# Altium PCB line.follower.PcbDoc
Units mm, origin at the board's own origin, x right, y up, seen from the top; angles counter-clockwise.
Board outline 60.32 x 63.12 mm, 2 copper layers (Top Layer, Bottom Layer); 13 components, 26 nets, 91 pads, 0 vias.
Unrouted connection lines stored in the file: 2.
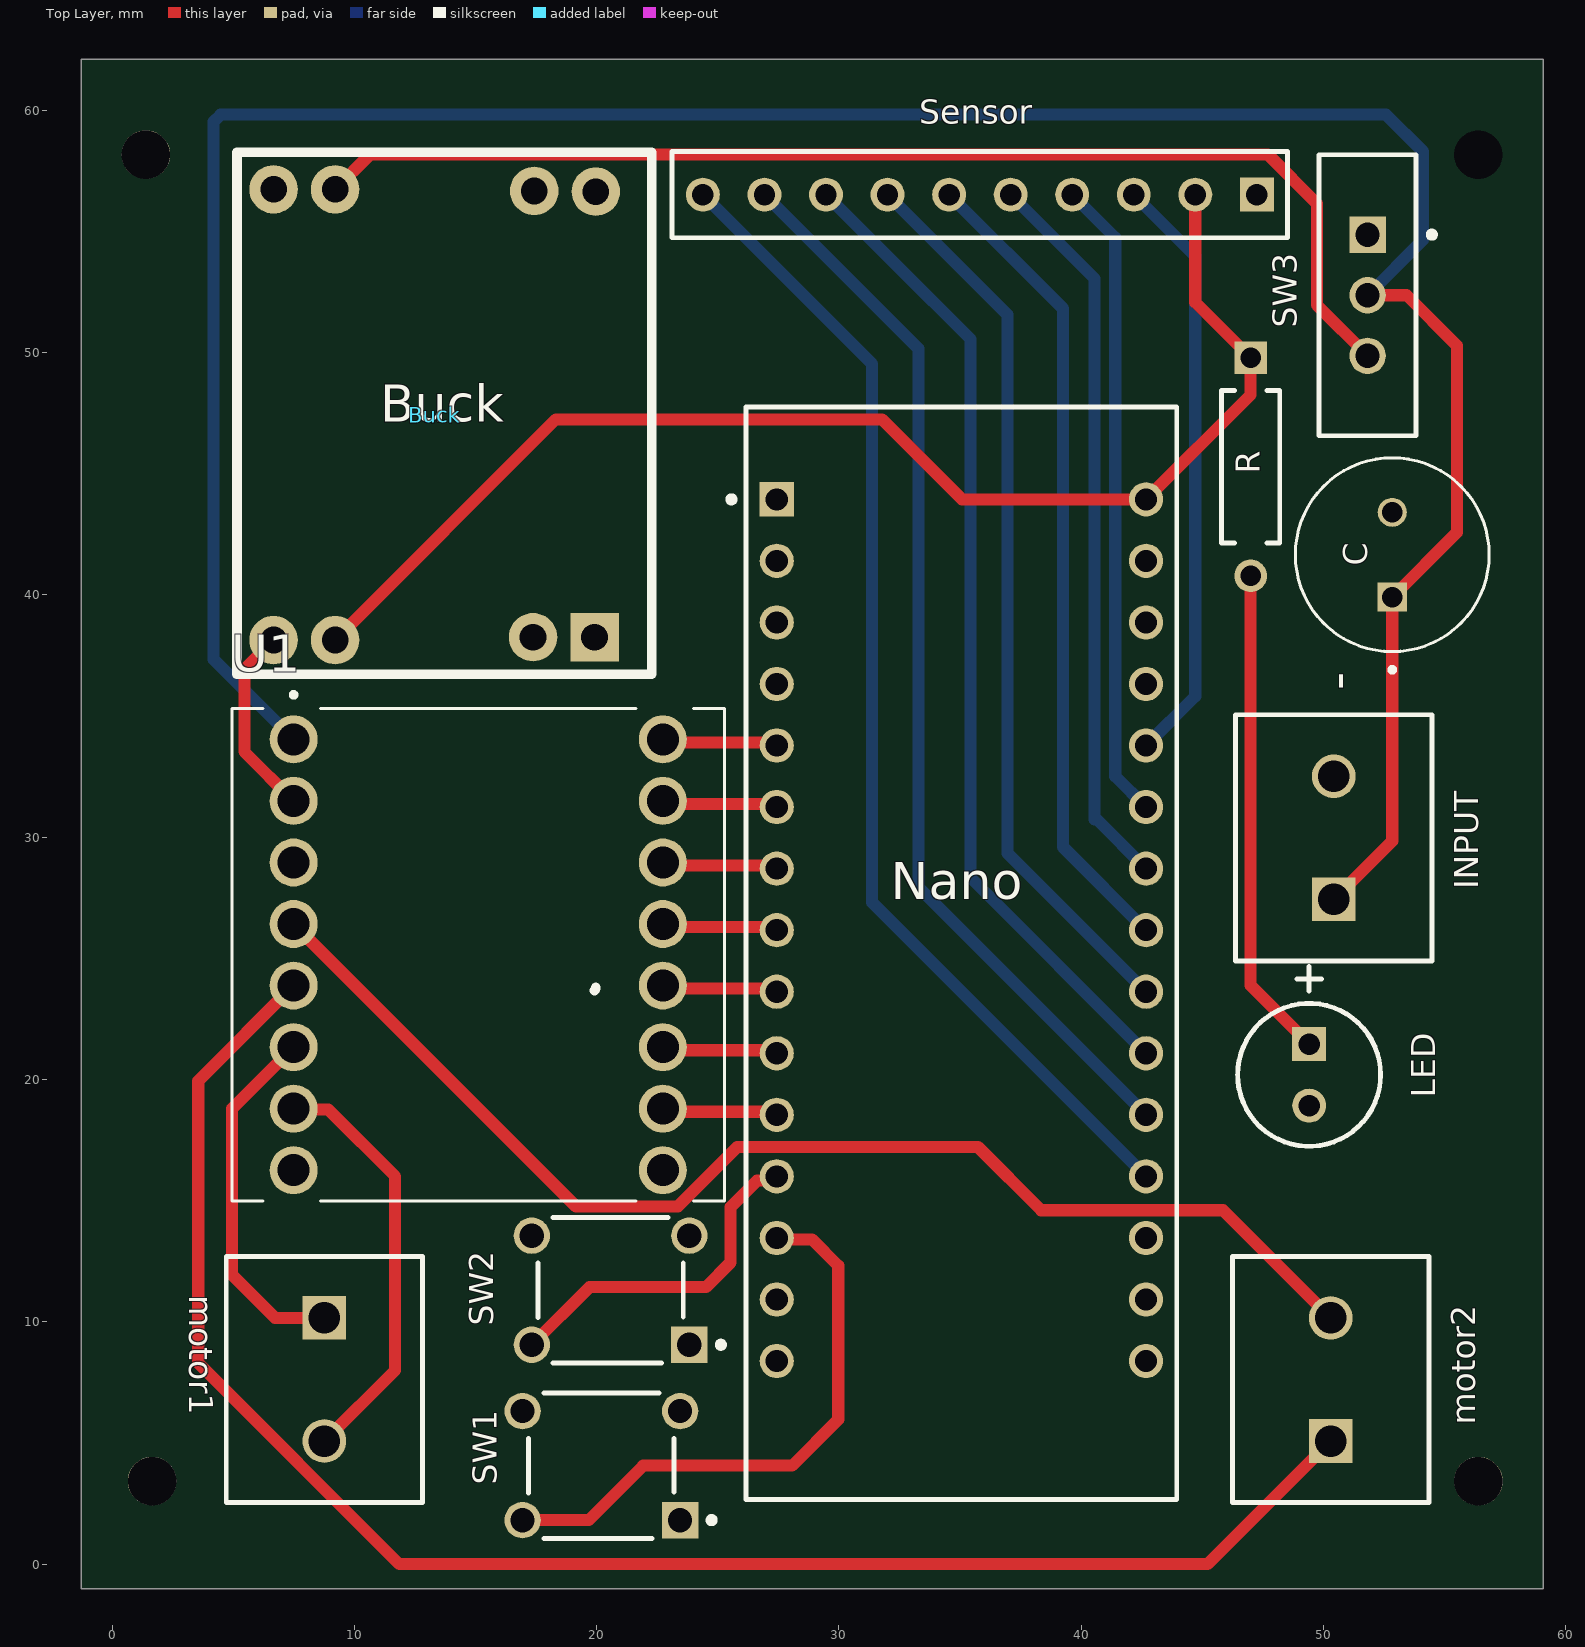
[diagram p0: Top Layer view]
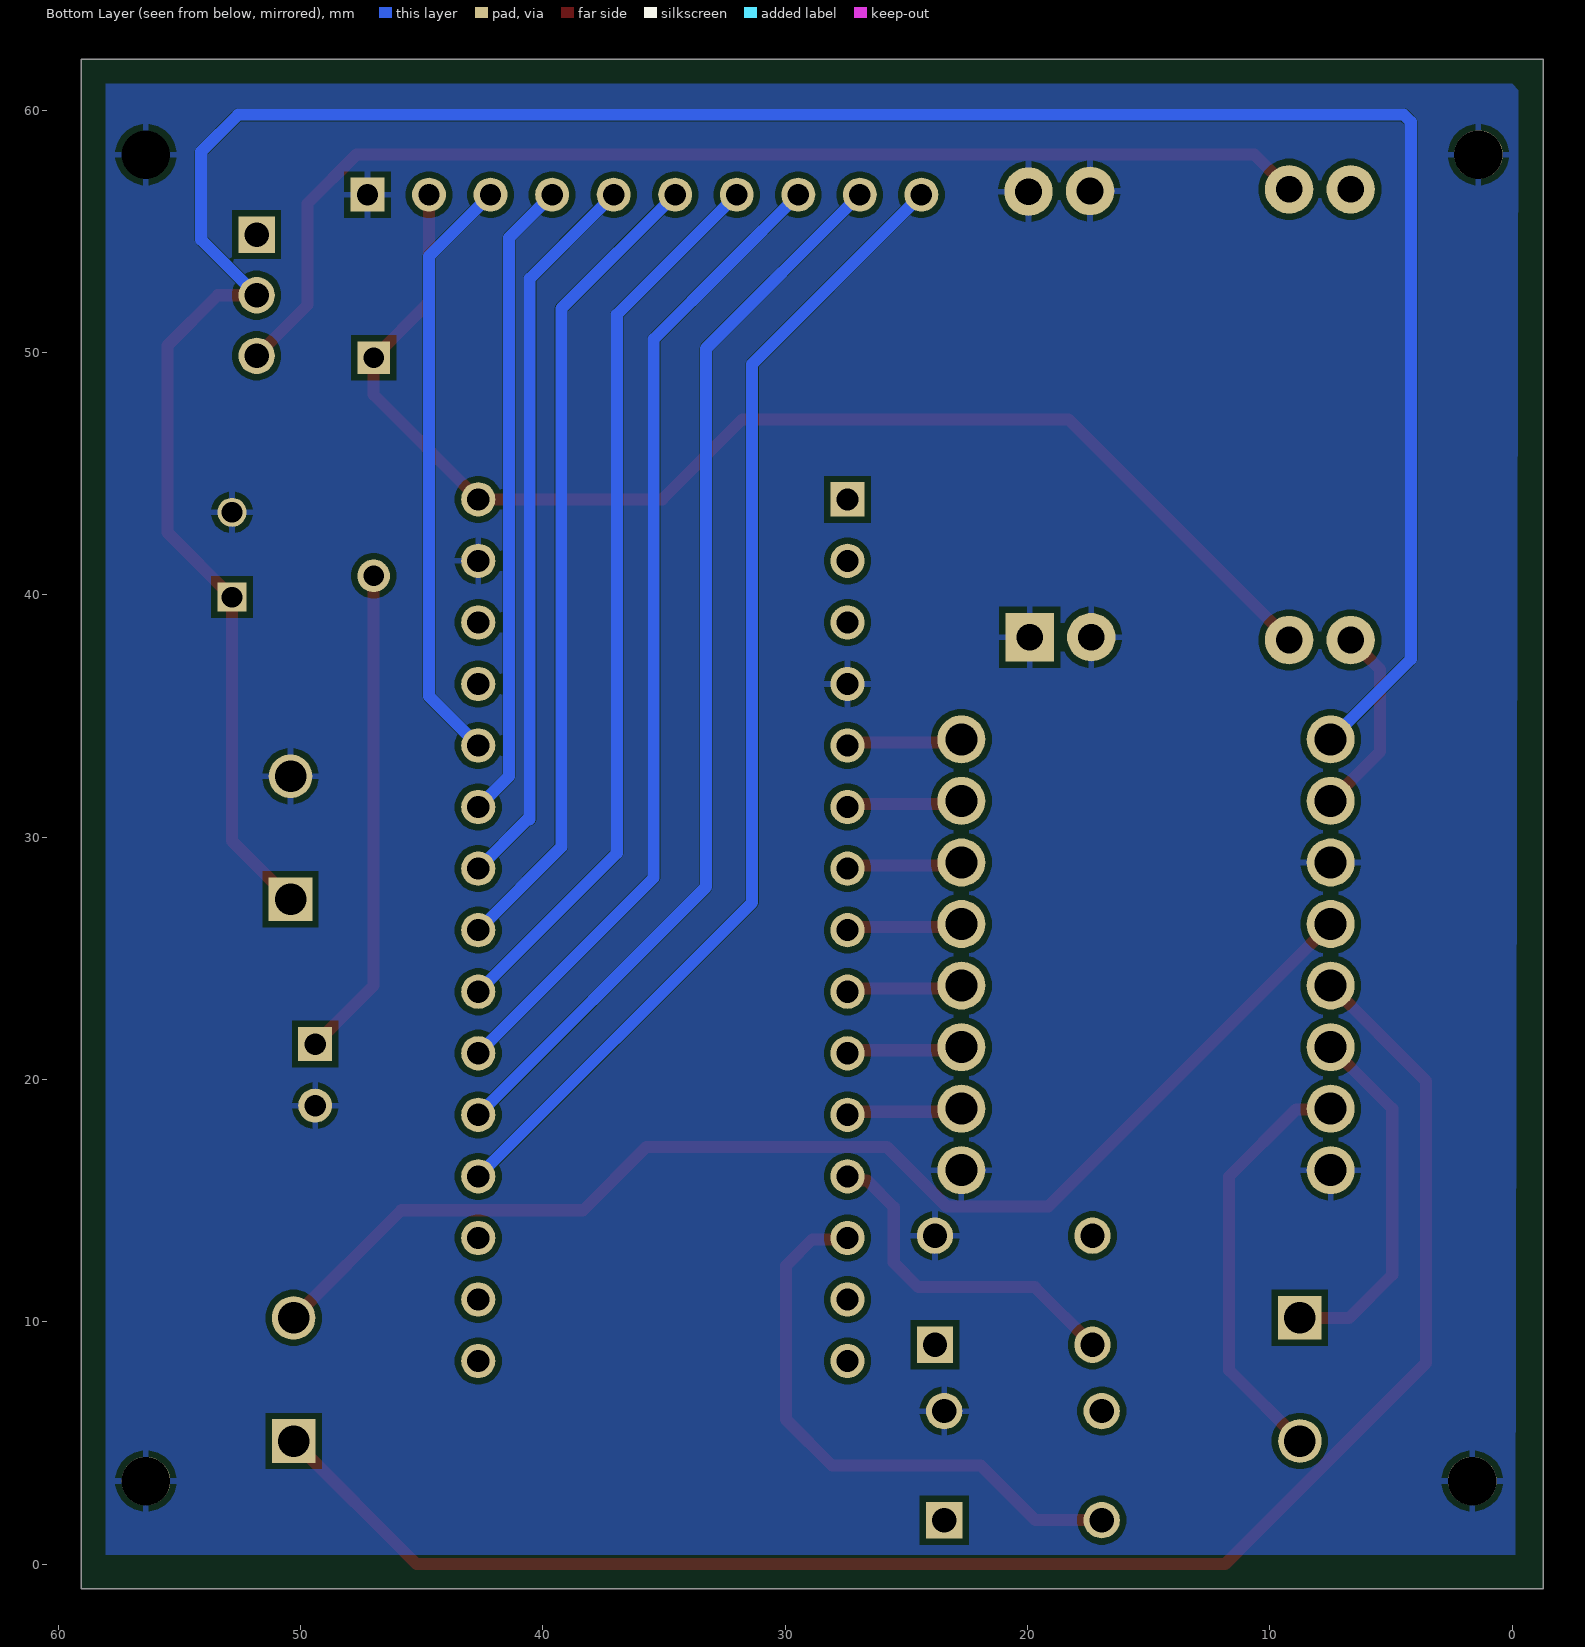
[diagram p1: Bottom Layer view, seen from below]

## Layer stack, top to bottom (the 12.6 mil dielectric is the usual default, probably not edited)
Top Solder: solder mask 0.0102, Solder Resist, Dk 3.5
Top Layer: signal copper 0.0356
Dielectric 1: dielectric 0.32, FR-4, Dk 4.8
Bottom Layer: signal copper 0.0356
Bottom Solder: solder mask 0.0102, Solder Resist, Dk 3.5

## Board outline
-1.27,-1.016 -1.27,62.103 59.055,62.103 59.055,-1.016

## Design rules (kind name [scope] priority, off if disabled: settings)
Clearance [All] p1: gap=0.254 ignorepadtopadclearanceinfootprint=FALSE except(0: Arc-Hole Track-Hole SMDPad-Hole THPad-Hole Via-Hole Fill-Hole Poly-Hole Region-Hole Text-Hole; 0.01: Arc-SMDPad Arc-THPad Arc-Via Arc-Fill Arc-Poly Arc-Region Arc-Text Track-SMDPad Track-THPad Track-Via Track-Fill Track-Poly Track-Region Track-Text)
PolygonConnect [All] p1: connectstyle=Relief reliefconductorwidth=0.254 reliefentries=4 polygonreliefangle="90 Angle" airgapwidth=0.254
RoutingVias [All] p1: holewidth=0.711 width=1.27 viastyle="Through Hole" minholewidth=0.711 minwidth=1.27 maxholewidth=0.711 maxwidth=1.27
SolderMaskExpansion [All] p1: expansion=0.102 istentingtop=FALSE
Width [All] p1: maxlimit=0.5 minlimit=0.5 preferedwidth=0.5 minimp=50.000000 maximp=50.000000 favimp=50.000000
30 further rules are at their usual default settings.

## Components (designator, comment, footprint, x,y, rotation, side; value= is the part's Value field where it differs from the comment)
Buck "M" "mp1584 mini buck" 13.716,47.498 r180 top
C "ECA1VM221" CAPPRD350W60D800H1150 52.832,41.656 r90 top (schematic designator C?)
INPUT "1729128" PHOE-1729128-2_V 50.419,29.972 r90 top (schematic designator "Screw Terminal")
LED "WP7113SGD" KING-WP7113SGD_V 49.403,20.193 r270 top
motor1 "1729128" PHOE-1729128-2_V 8.763,7.62 r270 top
motor2 "1729128" PHOE-1729128-2_V 50.292,7.62 r90 top
Nano "A000005" FP-A000005-MFG 35.052,25.209 r0 top
R "MFR-25FBF52-1K" RESA60-630X240 46.99,45.284 r270 top value=1k (schematic designator Resistor)
Sensor "5-534237-8" TECO-5-534237-8_V 35.814,56.515 r180 top
SW1 "B3F-1000" OMRON-B3F-1000-4_V 20.193,4.064 r180 top
SW2 "B3F-1000" OMRON-B3F-1000-4_V 20.574,11.303 r180 top
SW3 "EG1218" ESWI-EG1218_V 51.816,52.364 r270 top
U1 "ROB-14450" MODULE_ROB-14450 15.113,25.146 r0 top

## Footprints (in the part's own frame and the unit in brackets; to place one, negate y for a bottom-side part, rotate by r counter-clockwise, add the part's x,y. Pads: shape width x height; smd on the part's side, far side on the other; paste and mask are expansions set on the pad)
CAPPRD350W60D800H1150 [mm]
  round 1.2 hole 0.85: N(1.75,0)
  rect 1.2x1.2 hole 0.85: P(-1.75,0)
  silkscreen extent -4.85,-4 4,4, body extent -4,-4 4,4, height 11.5
ESWI-EG1218_V [mm] "THD, 3-Leads, Body 11.6x4mm, Pitch 2.5mm"
  rect 1.5x1.5 hole 1: 1(-2.5,0)
  round 1.5 hole 1: 2(0,0) 3(2.5,0)
  silkscreen extent -5.8,-2 5.8,2.78, body extent -5.8,-2 5.8,2, height 7.4
FP-A000005-MFG [mil]
  rect 55.67x55.67 hole 35.98 paste-39370.1 mask+0: 1(-300,737.5)
  round 55.67 hole 35.98 paste-39370.1 mask+0: 2(-300,637.5) 3(-300,537.5) 4(-300,437.5) 5(-300,337.5) 6(-300,237.5) 7(-300,137.5) 8(-300,37.5) 9(-300,-62.5) 10(-300,-162.5) 11(-300,-262.5) 12(-300,-362.5) 13(-300,-462.5) 14(-300,-562.5) 15(-300,-662.5) 16(300,-662.5) 17(300,-562.5) 18(300,-462.5) 19(300,-362.5) 20(300,-262.5) 21(300,-162.5) 22(300,-62.5) 23(300,37.5) 24(300,137.5) 25(300,237.5) 26(300,337.5) 27(300,437.5) 28(300,537.5) 29(300,637.5) 30(300,737.5)
  silkscreen extent -379,-888 350,888, body extent -354,-891 354,891, height 10
KING-WP7113SGD_V [mm] "THD, 2-Leads, Dia 5.9mm, Body Length 8.6mm"
  rect 1.4x1.4 hole 0.889: 1(-1.27,0)
  round 1.4 hole 0.889: 2(1.27,0)
  silkscreen extent -4.47,-2.95 2.95,2.95, body extent -2.95,-2.95 2.5,2.95, height 15.5
MODULE_ROB-14450 [mm]
  round 1.98 hole 1.32: 1(-7.62,8.89) 2(-7.62,6.35) 3(-7.62,3.81) 4(-7.62,1.27) 5(-7.62,-1.27) 6(-7.62,-3.81) 7(-7.62,-6.35) 8(-7.62,-8.89) 9(7.62,-8.89) 10(7.62,-6.35) 11(7.62,-3.81) 12(7.62,-1.27) 13(7.62,1.27) 14(7.62,3.81) 15(7.62,6.35) 16(7.62,8.89)
  silkscreen extent -10.16,-10.16 10.16,10.83, body extent -10.16,-10.16 10.16,10.16, height 5.5
"mp1584 mini buck" [mm]
  round 2 hole 1.1: "IN_N a"(-6.248,-9.144) "IN_N b"(-3.708,-9.169) "IN_P a"(4.509,-9.236) "IN_P b"(7.049,-9.236) "OUT_N b"(-3.658,9.246) "OUT_P a"(4.508,9.364) "OUT_P b"(7.048,9.364)
  rect 2x2 hole 1.1: "OUT_N a"(-6.198,9.246)
  silkscreen extent -8.56,-10.77 8.56,23.83, body extent -7.99,-11.02 8.81,11.08, height 5.51
OMRON-B3F-1000-4_V [mm] "TH, 4-Leads, Body 6x6mm"
  rect 1.5x1.5 hole 1 paste+0: 1(-3.25,2.25)
  round 1.5 hole 1 paste+0: 2(3.25,2.25) 4(3.25,-2.25)
  round 1.5 hole 1 paste+0 mask+0.102: 3(-3.25,-2.25)
  silkscreen extent -4.68,-3 3,3, body extent -3.4,-3 3.4,3, height 4.5
PHOE-1729128-2_V [mm] "Receptacle, 2-Leads, Body 8.1x10.16mm, Pitch 5.08mm"
  rect 1.8x1.8 hole 1.3: 1(-2.54,0)
  round 1.8 hole 1.3: 2(2.54,0)
  silkscreen extent -5.08,-4.05 5.08,4.05, body extent -5.65,-4.05 5.08,4.05, height 10.01
RESA60-630X240 [mm] "Axial Resistor, 2-Leads, Dia 2.4mm, Body Length 6.3mm"
  rect 1.35x1.35 hole 0.85: 1(-4.5,0)
  round 1.35 hole 0.85: 2(4.5,0)
  silkscreen extent -3.15,-1.2 3.15,1.2, body extent -4.77,-1.19 4.77,1.2, height 2.4
TECO-5-534237-8_V [mm] "Receptacle, 10-Leads, Body 25.4x3.56mm, Pitch 2.54mm"
  rect 1.4x1.4 hole 0.88: 1(-11.43,0)
  round 1.4 hole 0.88: 2(-8.89,0) 3(-6.35,0) 4(-3.81,0) 5(-1.27,0) 6(1.27,0) 7(3.81,0) 8(6.35,0) 9(8.89,0) 10(11.43,0)
  silkscreen extent -12.7,-1.78 12.7,1.78, body extent -12.7,-1.78 12.7,1.78, height 8.65

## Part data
Buck: library part "MP1584 mini buck module"
C: "220F 35V Aluminum Electrolytic Capacitors Radial, Can 2000 Hrs @ 85C", Package="RADIAL-2 Panasonic"
INPUT motor1 motor2: library part CMP-2000-05815-1, "PCB Terminal Block, 13.5 A, 400 V, 2-Pin THD, RoHS, Bulk", Current Rating=13500mA, Manufacturer="Phoenix Contact", Package Description="2-Pin Through Hole Device, Body 8.1 x 10.16 mm, Pitch 5.08 mm", Package Reference=1729128-2, Package Version=03/2015, Voltage Rating=400V
LED: library part CMP-007-00010-2, "LED Green, 62.5 mW, 25 mA, -40 to 85 degC, 2-Pin THD, RoHS, Bulk", Case/Package=Radial, Colour=Green, Forward Voltage=2.2V, Manufacturer=Kingbright, Package Description="2-Pin Through Hole Device, Dia 5.9 mm, Body Length 8.6 mm", Package Quantity=1000, Power=62.5mW
Nano: library part CMP-189986-000002-1, "ARDUINO NANO ATMEGA328 EVAL BRD", Operating Supply Voltage=12V, Package Quantity=50
R: library part CMP-009-00048-4, "Axial Resistor, 1 KOhm, +/- 1%, 250 mW, -55 to 155 degC, 2-Pin THD, RoHS, Bulk", Case/Package=Axial, Manufacturer=Yageo, Max Operating Temperature=155°C, Min Operating Temperature=-55°C, Package Description="2-Pin Axial Lead, Dia 2.4 mm, Body Length 6.3 mm", Package Quantity=200, Package Reference=MFR-25, Power=250mW, Tolerance=1%, Voltage Rating=250V
Sensor: library part CMP-002-00019-2, "Female Receptacle, Pitch 2.54 mm, 1 x 10 Position, Height 8.64 mm, Tail Length 2.92 mm, -65 to 105 degC, RoHS, Tube", Colour=Black, Current Rating=2A, Manufacturer="TE Connectivity", Max Contact Resistance=12mohm, Max Operating Temperature=105°C, Min Operating Temperature=-65°C, Package Description="Female Receptacle, Pitch 2.54 mm, 1 x 10 Position, Height 8.64 mm, Tail Length 2.92 mm", Package Quantity=22, Voltage Rating=750V
SW1 SW2: library part CMP-011-00004-2, "Tactile Switch, SPST-NO, 0.05 A, 24 V, -25 to 70 degC, 4-Pin THD, RoHS, Bulk", Contact Current Rating=50mA, Manufacturer="Omron Electronic Components", Max Contact Resistance=100mohm, Max Operating Temperature=70°C, Max Voltage Rating (DC)=24V, Min Operating Temperature=-25°C, Operating Force=100gf, Package Description="4-Pin Through Hole Device, Body 6 x 6 mm", Package Quantity=1500, Resistance=0.1Ohm
SW3: library part CMP-011-00006-2, "Slide Switch, SPDT, 500 V, -20 to 70 degC, 3-Pin THD, RoHS, Bulk", Contact Current Rating=200mA, Manufacturer=E-Switch, Max Operating Temperature=70°C, Min Operating Temperature=-20°C, Operating Force=250gf, Package Description="3-Pin Through Hole Device, Body 11.6 x 4 mm, Pitch 2.5 mm", Package Quantity=1000, Voltage Rating (AC)=30V
U1: library part CMP-00024-00006-1, "TB6612FNG Motor Controller/Driver Power Management Evaluation Board", Case/Package=None

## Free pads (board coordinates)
  round 1.524 hole 2: 4(56.388,58.166)
  round 2 hole 2: 5(56.388,3.429) 6(1.651,3.429) 7(1.397,58.166)

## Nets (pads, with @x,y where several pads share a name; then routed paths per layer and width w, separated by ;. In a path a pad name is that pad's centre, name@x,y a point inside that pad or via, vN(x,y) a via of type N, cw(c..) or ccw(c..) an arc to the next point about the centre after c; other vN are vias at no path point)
12V: C.P INPUT.1 SW3.2 U1.1 | length 113.9
  Top Layer w0.5: INPUT.1 52.832,29.845 C.P 55.499,42.573 55.499,50.292 53.427,52.364 SW3.2
  Bottom Layer w0.5: U1.1 4.191,37.338 4.191,42.885 4.191,59.524 4.484,59.817 52.578,59.817 54.102,58.293 54.102,54.65 SW3.2
A0: Nano.19 Sensor.10 | length 48.1
  Bottom Layer w0.5: Sensor.10 31.369,49.53 31.369,27.305 Nano.19
A1: Nano.20 Sensor.9 | length 44.5
  Bottom Layer w0.5: Sensor.9 33.274,50.165 33.274,27.94 Nano.20
A2: Nano.21 Sensor.8 | length 40.9
  Bottom Layer w0.5: Sensor.8 32.344,53.635 35.433,50.546 35.433,28.321 Nano.21
A3: Nano.22 Sensor.7 | length 37.3
  Bottom Layer w0.5: Sensor.7 36.957,51.562 36.957,29.337 Nano.22
A4: Nano.23 Sensor.6 | length 33.7
  Bottom Layer w0.5: Sensor.6 39.243,51.816 39.243,29.591 Nano.23
A5: Nano.24 Sensor.5 | length 30.2
  Bottom Layer w0.5: Sensor.5 40.552,53.047 40.552,30.734 40.64,30.734 Nano.24
A6: Nano.25 Sensor.4 | length 26.5
  Bottom Layer w0.5: Sensor.4 41.402,54.737 41.402,32.512 Nano.25
A7: Nano.26 Sensor.3 | length 24.6
  Bottom Layer w0.5: Sensor.3 44.704,53.975 44.704,35.814 Nano.26
AI1: Nano.7 U1.14 | length 4.8
  Top Layer w0.5: U1.14 22.86,28.829 27.305,28.829 Nano.7
AI2: Nano.6 U1.15 | length 4.8
  Top Layer w0.5: U1.15 22.86,31.369 27.305,31.369 Nano.6
BI1: Nano.9 U1.12 | length 4.8
  Top Layer w0.5: U1.12 22.86,23.749 27.305,23.749 Nano.9
BI2: Nano.10 U1.11 | length 4.8
  Top Layer w0.5: U1.11 22.86,21.209 27.305,21.209 Nano.10
GND: "Buck.IN_N a" "Buck.IN_N b" "Buck.OUT_N a" "Buck.OUT_N b" C.N INPUT.2 LED.2 Nano.4 Nano.29 pad.4 pad.5 pad.6 pad.7 Sensor.1 SW1.3 SW2.3 U1.3 U1.8 U1.9
"IN Pa": "Buck.IN_P a" "Buck.IN_P b" SW3.3 | length 49.1
  Top Layer w0.5: 9.207,56.734 10.644,58.171 47.7,58.171 49.726,56.146 49.726,51.954 SW3.3
LED: LED.1 R.2 | length 20.3
  Top Layer w0.5: R.2 46.99,23.876 LED.1
M1_1: motor2.2 U1.4 | length 51.6
  Top Layer w0.5: U1.4 19.147,14.762 23.352,14.762 25.803,17.213 35.734,17.213 38.342,14.605 45.847,14.605 motor2.2
M1_2: motor2.1 U1.5 | length 69.5
  Top Layer w0.5: U1.5 3.556,19.939 3.556,8.301 11.857,0 45.212,0 motor2.1
M2_1: motor1.2 U1.7 | length 17.5
  Top Layer w0.5: U1.7 7.525,18.764 8.922,18.764 11.684,16.002 11.684,8.001 motor1.2
M2_2: motor1.1 U1.6 | length 15
  Top Layer w0.5: U1.6 4.953,18.796 4.953,11.938 6.731,10.16 motor1.1
PWMA: Nano.5 U1.16 | length 4.8
  Top Layer w0.5: U1.16 22.86,33.909 27.305,33.909 Nano.5
PWMB: Nano.11 U1.10 | length 4.8
  Top Layer w0.5: U1.10 22.86,18.669 27.305,18.669 Nano.11
STBY: Nano.8 U1.13 | length 4.8
  Top Layer w0.5: U1.13 22.86,26.289 27.305,26.289 Nano.8
SW1: Nano.12 SW2.2 | length 14.3
  Top Layer w0.5: SW2.2 19.701,11.43 24.511,11.43 25.527,12.446 25.527,14.732 26.622,15.827 27.257,15.827 Nano.12
SW2: Nano.13 SW1.2 | length 24.1
  Top Layer w0.5: SW1.2 19.674,1.814 21.924,4.064 28.067,4.064 29.972,5.969 29.972,12.319 28.889,13.402 27.492,13.402 Nano.13
Vcc: "Buck.OUT_P a" "Buck.OUT_P b" Nano.30 R.1 Sensor.2 U1.2 | length 61.9
  Top Layer w0.5: 6.667,38.134 5.461,36.928 5.461,33.528 U1.2 ; 9.207,38.134 18.317,47.244 31.774,47.244 35.076,43.942 Nano.30 46.99,48.26 R.1 44.704,52.07 Sensor.2
pads on no net: Nano.1 Nano.2 Nano.3 Nano.14 Nano.15 Nano.16 Nano.17 Nano.18 Nano.27 Nano.28 SW1.1 SW1.4 SW2.1 SW2.4 SW3.1

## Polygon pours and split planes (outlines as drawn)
GND on Bottom Layer "NONET_L-01_P-001" (solid, pour order 0): -0.254,60.833 0,61.087 58.039,61.087 58.039,0.381 -0.127,0.381

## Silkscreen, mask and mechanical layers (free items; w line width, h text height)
Top Overlay:
  text "-" at 51.308,36.068 h1.52 r90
